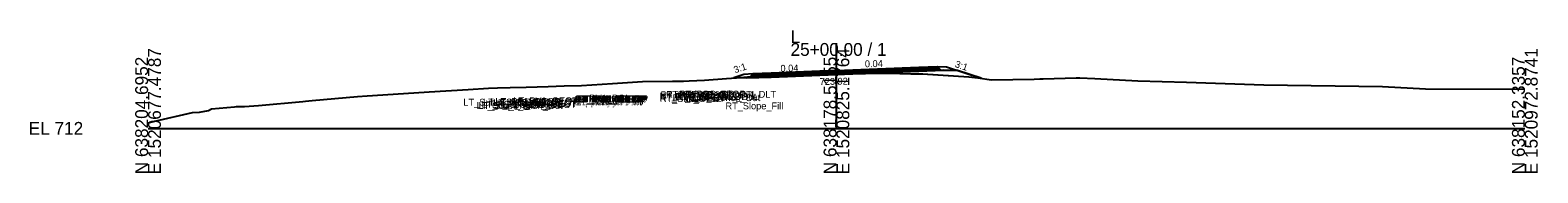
# Model space of a CAD drawing. Extents: x -26 to 3903, y -10 to 9531.
# Drawn here: x 974.3 to 1302.8, y 4990.3 to 5021.4 of the extents above; entities that cross this region are included whole.
import ezdxf

# ---------------------------------------------------------------- set-up
doc = ezdxf.new("R2010")
doc.units = 0
for name, color, linetype in [('Default', 7, 'Continuous'), ('Exist Cross Section Cell', 7, 'Continuous'), ('Exist XS Center Line Elevation Label', 7, 'Continuous'), ('Exist XS Ground Line', 7, 'Continuous'), ('Prop CMT Conc Surface', 7, 'Continuous'), ('Prop CMT Pvmt Course 1', 7, 'Continuous'), ('Prop CMT Pvmt Course 2', 7, 'Continuous'), ('Prop CMT Pvmt Course 3', 7, 'Continuous'), ('Prop CMT Pvmt Surface', 7, 'Continuous'), ('Prop CMT Pvmt Surface Shoulder', 7, 'Continuous'), ('Prop CMT Shld Paved Course 1', 7, 'Continuous'), ('Prop CMT Shld Paved Course 2', 7, 'Continuous'), ('Prop CMT Shld Paved Course 3', 7, 'Continuous'), ('Prop CMT Slope Grass', 7, 'Continuous'), ('Prop CMT Subgrade Earthwork', 7, 'Continuous'), ('Prop XS Earthwork Shape', 7, 'Continuous'), ('Prop XS SE Text', 7, 'Continuous'), ('Prop XS Side Slope Text', 7, 'Continuous')]:
    doc.layers.add(name, color=color, linetype=linetype)

msp = doc.modelspace()

# ---------------------------------------------------------------- linework, layer by layer
at = {"layer": 'Exist Cross Section Cell'}
for p, q in [((1150, 5000), (1150, 5018.6)), ((1000, 5000), (1150, 5000)), ((1150, 5000), (1300, 5000))]:
    msp.add_line(p, q, dxfattribs=at)
at = {"layer": 'Exist XS Ground Line'}
msp.add_lwpolyline([(1000, 5001.2), (1001.5, 5001.56), (1009.65, 5003.43), (1011.21, 5003.56), (1013.16, 5003.88), (1013.82, 5004.29), (1018.86, 5004.69), (1019.26, 5004.75), (1021, 5004.78), (1024.07, 5004.99), (1033.7, 5005.84), (1034.33, 5005.91), (1035.74, 5006.04), (1045.64, 5006.94), (1047.75, 5007.12), (1055.64, 5007.61), (1061.23, 5007.97), (1069.74, 5008.5), (1074.16, 5008.78), (1076.18, 5008.87), (1078.93, 5008.93), (1082.39, 5008.96), (1087.22, 5009.13), (1090.7, 5009.24), (1094.42, 5009.34), (1101.18, 5009.8), (1107.74, 5010.21), (1114.3, 5010.29), (1116.64, 5010.3), (1117.9, 5010.39), (1121.27, 5010.53), (1126.02, 5010.86), (1128.21, 5011.03), (1131.44, 5011.28), (1136.99, 5011.68), (1138.26, 5011.79), (1138.61, 5011.83), (1138.93, 5011.86), (1140.04, 5011.87), (1141.11, 5011.88), (1142.49, 5011.9), (1143.65, 5011.92), (1145.31, 5011.9), (1146.19, 5011.9), (1148.39, 5011.91), (1148.72, 5011.91), (1148.94, 5011.91), (1150, 5011.92), (1150.22, 5011.93), (1151.24, 5011.94), (1151.47, 5011.94), (1153.55, 5011.95), (1153.56, 5011.96), (1153.92, 5011.95), (1155.39, 5011.96), (1156.31, 5011.97), (1157.61, 5012), (1158.84, 5012.02), (1160.72, 5012), (1161.39, 5012), (1163.81, 5011.95), (1163.93, 5011.95), (1164.01, 5011.95), (1164.5, 5011.94), (1166.2, 5011.92), (1166.48, 5011.92), (1167.57, 5011.91), (1167.61, 5011.91), (1167.62, 5011.91), (1168.78, 5011.88), (1168.79, 5011.88), (1168.81, 5011.88), (1178.86, 5011.21), (1180.84, 5011.01), (1183.82, 5010.6), (1193.06, 5010.75), (1194.3, 5010.79), (1195.06, 5010.8), (1202.25, 5011), (1203.01, 5010.98), (1206.32, 5010.88), (1215.65, 5010.38), (1226.25, 5010.05), (1243.13, 5009.5), (1268.98, 5009.11), (1278.39, 5008.63), (1300, 5008.57)], dxfattribs=at)
at = {"layer": 'Prop CMT Pvmt Course 1'}
for points in [[(1149.97, 5012.59), (1135.81, 5012.03)], [(1135.81, 5011.78), (1149.97, 5012.34)], [(1135.81, 5012.03), (1135.81, 5011.78)], [(1149.97, 5012.59), (1167.95, 5013.31)], [(1167.95, 5013.06), (1149.97, 5012.34)], [(1149.97, 5012.34), (1149.97, 5012.59)], [(1149.97, 5012.34), (1149.97, 5012.59)], [(1167.95, 5013.31), (1167.95, 5013.06)]]:
    msp.add_lwpolyline(points, dxfattribs=at)
msp.add_lwpolyline([(1149.97, 5012.34), (1149.97, 5012.47), (1149.97, 5012.47), (1149.97, 5012.34)], close=True, dxfattribs=at)
msp.add_lwpolyline([(1149.97, 5012.34), (1149.97, 5012.47), (1149.97, 5012.47), (1149.97, 5012.34)], close=True, dxfattribs=at)
at = {"layer": 'Prop CMT Pvmt Course 2'}
for points in [[(1149.97, 5012.34), (1135.81, 5011.78)], [(1135.81, 5011.44), (1149.97, 5012.01)], [(1135.81, 5011.78), (1135.81, 5011.44)], [(1149.97, 5012.34), (1167.95, 5013.06)], [(1167.95, 5012.73), (1149.97, 5012.01)], [(1149.97, 5012.01), (1149.97, 5012.34)], [(1149.97, 5012.01), (1149.97, 5012.34)], [(1167.95, 5013.06), (1167.95, 5012.73)]]:
    msp.add_lwpolyline(points, dxfattribs=at)
at = {"layer": 'Prop CMT Pvmt Course 3'}
for points in [[(1149.97, 5012.01), (1135.81, 5011.44)], [(1135.81, 5011.19), (1149.97, 5011.76)], [(1135.81, 5011.44), (1135.81, 5011.19)], [(1149.97, 5012.01), (1167.95, 5012.73)], [(1167.95, 5012.48), (1149.97, 5011.76)], [(1149.97, 5011.76), (1149.97, 5012.01)], [(1149.97, 5011.76), (1149.97, 5012.01)], [(1167.95, 5012.73), (1167.95, 5012.48)]]:
    msp.add_lwpolyline(points, dxfattribs=at)
at = {"layer": 'Prop CMT Pvmt Surface'}
for points in [[(1149.97, 5012.59), (1135.81, 5012.03)], [(1149.97, 5012.59), (1167.95, 5013.31)]]:
    msp.add_lwpolyline(points, dxfattribs=at)
at = {"layer": 'Prop CMT Pvmt Surface Shoulder'}
for points in [[(1167.95, 5013.31), (1171.95, 5013.47)], [(1135.81, 5012.03), (1131.81, 5011.87)]]:
    msp.add_lwpolyline(points, dxfattribs=at)
at = {"layer": 'Prop CMT Shld Paved Course 1'}
for points in [[(1167.95, 5013.31), (1171.95, 5013.47), (1172.19, 5013.23)], [(1135.81, 5012.03), (1131.81, 5011.87), (1131.55, 5011.61)], [(1131.55, 5011.61), (1135.81, 5011.78)], [(1135.81, 5011.78), (1135.81, 5012.03)], [(1167.95, 5013.06), (1167.95, 5013.31)], [(1172.19, 5013.23), (1167.95, 5013.06)]]:
    msp.add_lwpolyline(points, dxfattribs=at)
at = {"layer": 'Prop CMT Shld Paved Course 2'}
for points in [[(1135.81, 5011.78), (1131.55, 5011.61), (1131.21, 5011.26)], [(1131.21, 5011.26), (1135.81, 5011.44)], [(1135.81, 5011.44), (1135.81, 5011.78)], [(1167.95, 5013.06), (1172.19, 5013.23), (1172.51, 5012.91)], [(1167.95, 5012.73), (1167.95, 5013.06)], [(1172.51, 5012.91), (1167.95, 5012.73)]]:
    msp.add_lwpolyline(points, dxfattribs=at)
at = {"layer": 'Prop CMT Shld Paved Course 3'}
for points in [[(1130.45, 5010.98), (1135.81, 5011.19)], [(1135.81, 5011.44), (1131.21, 5011.26), (1130.94, 5011)], [(1135.81, 5011.19), (1135.81, 5011.44)], [(1167.95, 5012.73), (1172.51, 5012.91), (1172.75, 5012.67)], [(1167.95, 5012.48), (1167.95, 5012.73)], [(1173.25, 5012.69), (1167.95, 5012.48)]]:
    msp.add_lwpolyline(points, dxfattribs=at)
at = {"layer": 'Prop CMT Slope Grass'}
for points in [[(1171.95, 5013.47), (1173.95, 5013.43), (1181.51, 5010.91)], [(1131.81, 5011.87), (1129.81, 5011.71), (1127.65, 5010.99)]]:
    msp.add_lwpolyline(points, dxfattribs=at)
at = {"layer": 'Prop CMT Subgrade Earthwork'}
for points in [[(1130.45, 5010.98), (1127.65, 5010.99)], [(1135.81, 5011.19), (1130.45, 5010.98)], [(1149.97, 5011.76), (1135.81, 5011.19)], [(1149.97, 5011.76), (1167.95, 5012.48)], [(1167.95, 5012.48), (1173.25, 5012.69)], [(1173.25, 5012.69), (1176.36, 5012.63)]]:
    msp.add_lwpolyline(points, dxfattribs=at)
at = {"layer": 'Prop XS Earthwork Shape'}
for points in [[(1135.81, 5011.19), (1130.45, 5010.98), (1127.65, 5010.99), (1128.21, 5011.03), (1131.44, 5011.28), (1136.99, 5011.68), (1138.26, 5011.79), (1138.61, 5011.83), (1138.93, 5011.86), (1140.04, 5011.87), (1141.11, 5011.88), (1142.49, 5011.9), (1143.65, 5011.92), (1145.31, 5011.9), (1146.19, 5011.9), (1148.39, 5011.91), (1148.72, 5011.91), (1148.94, 5011.91), (1150, 5011.92), (1150.22, 5011.93), (1151.24, 5011.94), (1151.47, 5011.94), (1153.55, 5011.95), (1153.92, 5011.95), (1154.86, 5011.96), (1149.97, 5011.76)], [(1138.93, 5011.86), (1140.04, 5011.87), (1141.11, 5011.88), (1142.49, 5011.9), (1143.65, 5011.92), (1145.31, 5011.9), (1146.19, 5011.9), (1148.39, 5011.91), (1148.72, 5011.91), (1148.94, 5011.91), (1150, 5011.92), (1150.22, 5011.93), (1151.24, 5011.94), (1151.47, 5011.94), (1153.55, 5011.95), (1153.92, 5011.95), (1154.86, 5011.96), (1149.97, 5011.76), (1135.81, 5011.19), (1130.45, 5010.98), (1127.65, 5010.99), (1128.21, 5011.03), (1131.44, 5011.28), (1136.99, 5011.68), (1138.26, 5011.79), (1138.61, 5011.83)], [(1168.78, 5011.88), (1178.86, 5011.21), (1180.84, 5011.01), (1181.51, 5010.91), (1176.36, 5012.63), (1173.25, 5012.69), (1167.95, 5012.48), (1154.86, 5011.96), (1155.39, 5011.96), (1156.31, 5011.97), (1157.61, 5012), (1158.84, 5012.02), (1160.72, 5012), (1161.39, 5012), (1163.81, 5011.95), (1164.01, 5011.95), (1164.5, 5011.94), (1166.2, 5011.92), (1166.48, 5011.92), (1167.57, 5011.91)], [(1163.81, 5011.95), (1164.01, 5011.95), (1164.5, 5011.94), (1166.2, 5011.92), (1166.48, 5011.92), (1167.57, 5011.91), (1168.78, 5011.88), (1178.86, 5011.21), (1180.84, 5011.01), (1181.51, 5010.91), (1176.36, 5012.63), (1173.25, 5012.69), (1167.95, 5012.48), (1154.86, 5011.96), (1155.39, 5011.96), (1156.31, 5011.97), (1157.61, 5012), (1158.84, 5012.02), (1160.72, 5012), (1161.39, 5012)]]:
    msp.add_lwpolyline(points, close=True, dxfattribs=at)

# ---------------------------------------------------------------- texts
at = {"layer": 'Default'}
msp.add_text('-', height=0.0001, dxfattribs=at).set_placement((1000, 5000))
at = {"layer": 'Exist Cross Section Cell'}
for s, p in [('L', (1140, 5018.6)), ('25+00.00 / 1', (1140, 5015.8)), ('EL 712', (974, 4998.6))]:
    msp.add_text(s, height=2.8, dxfattribs=at).set_placement(p)
for s, p in [('E 1520677.4787', (1002.8, 4990)), ('E 1520825.1764', (1152.8, 4990)), ('E 1520972.8741', (1302.8, 4990)), ('N 638204.6952', (1000, 4990)), ('N 638178.5155', (1150, 4990)), ('N 638152.3357', (1300, 4990))]:
    msp.add_text(s, height=2.8, rotation=90, dxfattribs=at).set_placement(p)
at = {"layer": 'Exist XS Center Line Elevation Label'}
msp.add_text('723.92', height=1.5, rotation=0.8401, dxfattribs=at).set_placement((1146.36, 5009.45))
at = {"layer": 'Prop CMT Conc Surface'}
for s, p in [('RT_PV2_OEEOP', (1092.97, 5005.59)), ('LT_PV2_OEEOP', (1093.06, 5005.59)), ('RT_PV1_OEEOP', (1093.15, 5005.72)), ('LT_PV1_OEEOP', (1093.24, 5005.72)), ('RT_PV2_IEEOP', (1093.54, 5005.59)), ('LT_PV2_IEEOP', (1093.63, 5005.59)), ('RT_PV1_IEEOP', (1093.72, 5005.72)), ('LT_PV1_IEEOP', (1093.81, 5005.72)), ('PV2_PGL', (1095.99, 5005.59)), ('PV1_PGL', (1096.17, 5005.84)), ('RT_PV2_OEOT', (1111.48, 5006.31)), ('RT_PV3_OEOT', (1111.48, 5005.98)), ('RT_Sub_OEOT', (1111.52, 5005.73)), ('RT_PV1_OEOT', (1111.66, 5006.56)), ('RT_Sub_Trench_Out_DLT', (1112.88, 5006.68)), ('RT_Sub_Trench_Out', (1114.33, 5005.94)), ('RT_PS3_Shelf_Out', (1114.91, 5006.18)), ('RT_PS1_OEOP', (1115.72, 5006.72)), ('RT_PS2_OEOP', (1115.78, 5006.48)), ('RT_PS3_OEOP', (1116.1, 5006.16)), ('RT_GS_OS_CTL', (1117.06, 5006.68)), ('LT_Sub_Trench_Out_DLT', (1068.7, 5004.95)), ('LT_Sub_Trench_Out', (1071.61, 5004.23)), ('LT_Slope_Fill', (1072.02, 5004.24)), ('LT_PS3_Shelf_Out', (1072.69, 5004.49)), ('LT_GS_OS_CTL', (1073.01, 5004.96)), ('LT_PS3_OEOP', (1074.89, 5004.51)), ('LT_PS2_OEOP', (1075.23, 5004.86)), ('LT_PS1_OEOP', (1075.67, 5005.12)), ('LT_PV2_OEOT', (1079.43, 5005.03)), ('LT_PV3_OEOT', (1079.43, 5004.69)), ('LT_Sub_OEOT', (1079.47, 5004.44)), ('LT_PV1_OEOT', (1079.61, 5005.28)), ('RT_PV3_OEEOP', (1092.97, 5005.26)), ('RT_Sub_OEEOP', (1093, 5005.01)), ('LT_PV3_OEEOP', (1093.06, 5005.26)), ('LT_Sub_OEEOP', (1093.09, 5005.01)), ('RT_Slope_Fill', (1125.82, 5004.15))]:
    msp.add_text(s, height=1.5, dxfattribs=at).set_placement(p)
at = {"layer": 'Prop XS SE Text'}
for p in [(1137.82, 5012.33), (1156.21, 5013.31)]:
    msp.add_text('0.04', height=1.5, rotation=1.1458, dxfattribs=at).set_placement(p)
at = {"layer": 'Prop XS Side Slope Text'}
for rotation, p in [(18.4332, (1127.9, 5011.99)), (341.5668, (1175.7, 5013.4))]:
    msp.add_text('3:1', height=1.5, rotation=rotation, dxfattribs=at).set_placement(p)

doc.saveas('drawing.dxf')
